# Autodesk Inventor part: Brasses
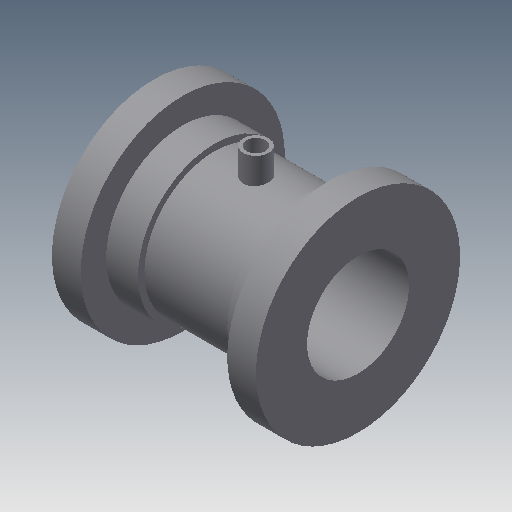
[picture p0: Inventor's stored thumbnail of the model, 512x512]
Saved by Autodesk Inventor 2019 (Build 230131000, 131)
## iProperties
Created: 2009-04
Part Number: Brasses
Document SubType Name: Modeling
Designer: Sham
Density: 1 g/cm^3
Material: Generic
Appearance: Default
Author: Sham
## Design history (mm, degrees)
sketch "Sketch1"
  geometry: L1 (0, 32)-(9, 32); L2 (0, 16)-(64, 16); L3 (64, 32)-(55, 32); L4 (55, 32)-(55, 24); L5 (55, 24)-(47, 24); L6 (19, 22)-(47, 22); L7 (47, 24)-(47, 22); L8 (19, 22)-(19, 24); L9 (19, 24)-(9, 24); L10 (9, 24)-(9, 32); L11 (0, 32)-(0, 16); L12 (64, 32)-(64, 16); L13 (-12.8, 0)-(76.8, 0) reference; 1 further point
  constraints: 24 end point, 7 parallel, 4 perpendicular, 1 collinear, 1 horizontal, 1 vertical alignment, 1 other
  dimensions: "d0" = 9 distance of L1.start L1.end; "d2" = 16 distance from line of L2 point (0, 0); "d3" = 64 distance of L2.start L2.end; "d4" = 24 distance from line of point (0, 0) L5; "d5" = 28 distance of L6.start L6.end; "d6" = 22 distance from line of point (0, 0) L6; "d7" = 8 distance of L4.end L5.end
revolve "Revolution1" sketch "Sketch1" stored, may be unused: angle "d8" = 90 deg
workplane "Work Plane1"
sketch "Sketch2"
  geometry: C1 r 4 at (-32, 0)
  constraints: 1 centre point
  dimensions: "d10" = 8 diameter of C1
extrude "Extrusion1" join sketch "Sketch2" stored distance "d11" = 10; taper "d12" = 0 deg
sketch "Sketch3"
  geometry: C1 r 4 at (0, 0) reference; C2 r 3 at (0, 0)
  constraints: 1 centre point, 1 coincident
  dimensions: "d13" = 6 diameter of C2
extrude "Extrusion2" cut sketch "Sketch3" extent not by distance; stored distance "d14" = 10; taper "d15" = 0 deg
body "Solid1"
